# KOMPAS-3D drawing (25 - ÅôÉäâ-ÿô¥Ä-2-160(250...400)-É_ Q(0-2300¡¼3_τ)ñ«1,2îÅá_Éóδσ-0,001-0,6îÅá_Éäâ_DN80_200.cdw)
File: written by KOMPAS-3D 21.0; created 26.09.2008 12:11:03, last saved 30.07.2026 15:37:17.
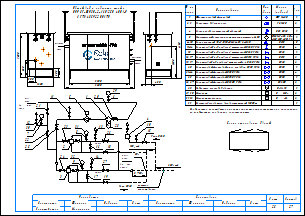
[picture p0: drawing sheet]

Sheets 1-2: A3, landscape

Document properties: Наименование: Макро:21; Автор: RaskoAdmin; Форматы листов документа: 2xA3; Полное имя файла: \\ur38nt01\Departments\КТО\КБ ПУРДГ\Заявки\Прайс-лист на типовые шкафы ГРПШ\ПУРДГ_стандарт_30_04_2026\ПУРДГ с РДГ(Н, В)\ПУРДГ-ШУЭО-2-160(250...400)-Р_ Q(0-2300нм3_ч)до1,2МПа_Рвых-0,001-0,6МПа_РДГ_DN80_200.cdw

Title block, sheet 1: Наименование: Пункт учета газа / ПУГ-Ш-400-Р / ЛГТИ.485922.001ТУ; designation: ЛГТИ.03.4411141; sheet number: 1; Количество листов документа: 2; organisation: ООО "ЭЛЬСТЕР Газэлектроника"; Форматы листов документа: A3; stored path: C:\Рабочие документы\Компас\ПУГ\Схема.cdw; Разработал: Устинов; Проверил: Кошкин; Утвердил: Кошкин
Title block, sheet 2: sheet number: 2; stored path: D:\Рабочие документы\Заявки\ПУРДГ\ПУРДГ-ШУЭО-2-100-Р 4411220.cdw; designation, second copy: ЛГТИ.03.4411141-

Views: Вид 1, Вид 2
Referenced files: wcvoit.frw
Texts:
  Normal
  № на
  схеме
  Усл.
  обозн.
  Марка
  (модель)
  Кол.
  Фильтр газовый фланцевый
  ФГ 16-80
  Регулятор давления газа
  РДГ-50
  Клапан предохранительный сбросной
  ПСК DN25
  Измерительный комплекс с ротационным счетчиком Ду50
  СГ-ЭК-Р-(0,2...2,0)-
  Кран кнопочный VE-РАСКО-НЗ-1,6-G1/2-М20
  DN15
  Кран шаровой "под приварку" штуцерный DN20 PN16
  Кран шаровой "под приварку" штуцерный DN25 PN16
  DN20
  DN25
  Кран шаровой "под приварку" штуцерный DN15 PN16
  Кран шаровой "под приварку" штуцерный п/п DN20 PN16
  Кран шаровой фланцевый с мех. приводом DN80 PN16
  Кран шаровой фланцевый DN50 PN16
  Кран шаровой фланцевый DN80 PN16
  Кран шаровой фланцевый DN200 PN16
  DN80
  DN50
  DN200
  Индикатор перепада давления
  Манометр
  Манометр-напоромер
  Электрообогреватель взрывозащищенный 1200Вт
  Delta 15
  0...     МПа
  0...     кПа
  Общий вид и габариты шкафа
  ПУРДГ-ШУЭО-2-160(250...400)-Р
  Выход газа
  Вход газа
  logo-rasko-ge.png
  DN 1
  местное
  сопротивление
  Римп DN20
  Выход
  газа
  Р=     кПа
  Вход
  Р=       МПа
  PDI
  Схема открывания дверей
  Предприятие изготовитель может заменять комплектующие на аналогичные,
  не ухудшающие заявленных характеристик.
  Должность
  Конструктор
  Фамилия
  Подпись
  Дата
  Согласовано
  Максимкин
  Лист
  Листов
  POLYLINE_STYLE_0.18_RGB_0_0_0
  POLYLINE_STYLE_0.50_RGB_0_0_0
  POLYLINE_STYLE_0.34_RGB_0_0_0
  PHANTOM_RGB_0_0_0_SC_1_THICK_0.18
  K5LT_THIN_RGB_0_0_0_THICK_0.18
  K5LT32769_RGB_0_0_0_THICK_0.18
  K5LT12_RGB_0_0_0_SC_1_THICK_0.18
  K5LT_DASHED_RGB_0_0_0_SC_1_THICK_0.18
  ACISOTGL_RGB_0_0_0_SC_0.8_THICK_0.25
  CONTINUOUS_RGB_0_127_31_THICK_0.3
  CONTINUOUS_RGB_0_0_255_THICK_0.35
  CONTINUOUS_RGB_255_0_0_THICK_0.35
  POLYLINE_STYLE_0.25_RGB_0_0_0
  CONTINUOUS_RGB_0_0_0_THICK_0.5
  POLYLINE_STYLE_0.35_RGB_0_0_255
  CONTINUOUS_RGB_0_0_0_THICK_0.4
  CONTINUOUS_RGB_0_0_0_THICK_0.35
  НЕВИДИМАЯ_RGB_0_0_0_SC_0.3_THICK_0.25
  СONTINUOUS_RGB_0_0_0_THICK_0.25
  ОСЕВАЯ2_RGB_248_153_30_SC_0.3_THICK_0.25
  Без оформления
Dimensions and other numbers on the sheet: 1; 2, 3; 2; 4; 5; -160 (250; 400)/1,6; 6-10; 11-14; 15; 16, 17; 18, 19; 20; 21-24; 25; 26, 27; 28; 29, 30; 31, 32; 33; 1500; 450; 500; 1200; 550; 305; 3300; 4130; 2000; 3600; 5,,,7DN 1; 7; 30; 12; 21; 22; 11; 6; 29; 23; 31; 8; 13; 26; 18; 10; 24; 32; 9; 3; 14; 27; 19; 16; 17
